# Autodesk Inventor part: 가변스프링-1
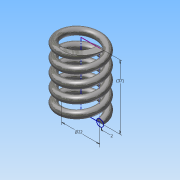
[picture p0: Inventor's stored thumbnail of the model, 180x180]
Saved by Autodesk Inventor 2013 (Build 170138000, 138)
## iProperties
Created: 2016-01
Part Number: 가변스프링-1
Material: 스테인리스강
Document SubType Name: Modeling
Designer: Administrator
Mass: 34.2793 g
Surface Area: 43.3134 cm^2
Volume: 4.24249 cm^3
Density: 8.08 g/cm^3
Author: Administrator
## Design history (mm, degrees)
sketch "스케치1"
  geometry: L1 (0, 0)-(11, 0); L2 (11, 0)-(11, 36.411); L3 (11, 36.411)-(0, 36.411); L4 (0, 36.411)-(0, 0); C1 r 2 at (11, 0)
  constraints: 8 end point, 2 parallel, 1 centre point, 1 coincident, 1 horizontal, 1 perpendicular
  dimensions: "d0" = 2 radius of C1; "d1" = 22 diameter of L2 L4; "d2" = 36.4112 distance between parallel lines of L3 L1 (derived)
feature "코일1" sketch "스케치1" pitch "d3" = 10; turns "d5" = 5; dims "d4" = 36.4112 (= d2), "d6" = 0, angle "d7" = 90 deg, angle "d8" = 90 deg, "d9" = 0, "d10" = 0
feature "분할1"
node "작업 평면1"
feature "분할2"
node "솔리드1"
other parameters: "d11" = 90 deg
